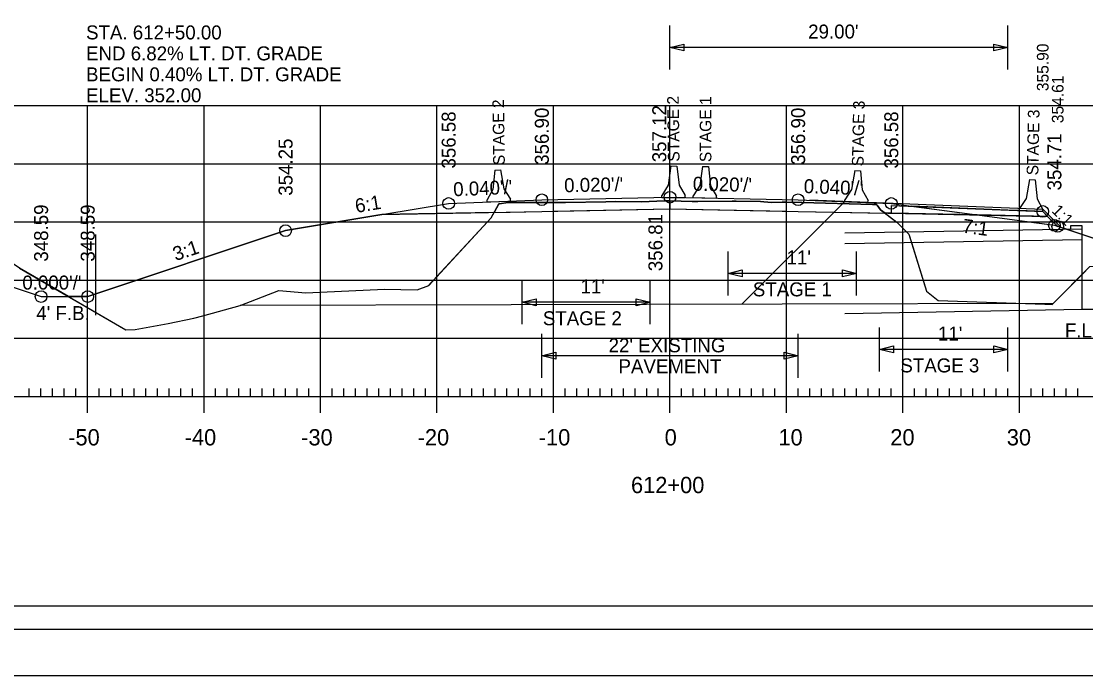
# Model space of a CAD drawing. Extents: x 1368910 to 1369601, y 380116 to 380950.
# Drawn here: x 1369381.9 to 1369473.3, y 380523.8 to 380580 of the extents above; entities that cross this region are included whole.
import ezdxf

# ---------------------------------------------------------------- set-up
doc = ezdxf.new("R2010")
doc.units = 0
for name, color, linetype in [('_STAGE 1 CUT', 7, 'Continuous'), ('_STAGE 1 FILL', 7, 'Continuous'), ('_STAGE 2 CUT', 7, 'Continuous'), ('_STAGE 2 FILL', 7, 'Continuous'), ('_STAGE 3 CUT', 7, 'Continuous'), ('_STAGE 3 FILL', 7, 'Continuous'), ('_STAGE 4 CUT', 7, 'Continuous'), ('Notes', 7, 'Continuous'), ('R_Alt Surface', 7, 'Continuous'), ('R_Axis', 7, 'Continuous'), ('R_Axis Annot', 7, 'Continuous'), ('R_Border', 7, 'Continuous'), ('R_CONC BARRIER', 7, 'Continuous'), ('R_Detour', 7, 'Continuous'), ('R_Detour Surface', 7, 'Continuous'), ('R_Exist Surface', 7, 'Continuous'), ('R_Fin Surface', 7, 'Continuous'), ('R_Grid', 7, 'Continuous'), ('R_No Plot', 7, 'Continuous'), ('R_ROW Annot', 7, 'Continuous'), ('R_Water', 7, 'Continuous'), ('R_Xsect Elev', 7, 'Continuous'), ('R_Xsect Elev Detour', 7, 'Continuous'), ('R_Xsect Slope', 7, 'Continuous')]:
    doc.layers.add(name, color=color, linetype=linetype)

msp = doc.modelspace()

# ---------------------------------------------------------------- linework, layer by layer
at = {"layer": '_STAGE 1 CUT'}
for p, q in [((1369437.59, 380563.882), (1369437.59, 380564.569)), ((1369383.605, 380556.347), (1369385.955, 380556.347))]:
    msp.add_line(p, q, dxfattribs=at)
for points in [[(1369437.59, 380564.569), (1369437.492, 380564.567), (1369437.319, 380564.562), (1369437.081, 380564.558), (1369435.172, 380564.496), (1369432.919, 380564.5), (1369432.093, 380564.495), (1369428.627, 380564.424), (1369428.439, 380564.418), (1369427.59, 380564.423), (1369426.908, 380564.427), (1369426.774, 380564.429), (1369426.749, 380564.429), (1369426.202, 380564.433), (1369423.661, 380564.418), (1369422.964, 380564.304), (1369422.899, 380564.322), (1369422.495, 380563.58)], [(1369422.495, 380563.58), (1369426.59, 380563.662), (1369427.59, 380563.682), (1369437.59, 380563.882)], [(1369385.955, 380556.347), (1369383.513, 380557.759), (1369381.75, 380558.778), (1369379.363, 380560.35), (1369377.59, 380560.372), (1369371.297, 380560.45)], [(1369371.297, 380560.45), (1369377.59, 380558.352), (1369379.37, 380557.759), (1369383.605, 380556.347)]]:
    msp.add_lwpolyline(points, dxfattribs=at)
at = {"layer": '_STAGE 1 FILL'}
for p, q in [((1369417.59, 380563.482), (1369412.863, 380563.388)), ((1369422.495, 380563.58), (1369417.59, 380563.482))]:
    msp.add_line(p, q, dxfattribs=at)
for points in [[(1369385.955, 380556.347), (1369390.879, 380553.501), (1369391.669, 380553.528), (1369394.515, 380554.027), (1369396.729, 380554.484), (1369397.501, 380554.702), (1369400.702, 380555.59), (1369404, 380556.859), (1369406.338, 380556.674), (1369413.073, 380556.969), (1369415.896, 380556.934), (1369416.88, 380557.303), (1369417.3, 380557.759), (1369417.59, 380558.073), (1369421.913, 380562.759), (1369422.243, 380563.116), (1369422.495, 380563.58)], [(1369412.863, 380563.388), (1369409.09, 380562.759), (1369404.59, 380562.009), (1369391.84, 380557.759), (1369387.605, 380556.347), (1369385.955, 380556.347)]]:
    msp.add_lwpolyline(points, dxfattribs=at)
at = {"layer": '_STAGE 2 CUT'}
msp.add_line((1369437.59, 380564.569), (1369437.59, 380563.882), dxfattribs=at)
for points in [[(1369447.53, 380564.453), (1369447.214, 380564.45), (1369446.346, 380564.419), (1369445.651, 380564.495), (1369445.362, 380564.504), (1369443.277, 380564.539), (1369443.146, 380564.539), (1369443.067, 380564.534), (1369442.935, 380564.541), (1369439.984, 380564.51), (1369439.666, 380564.51), (1369439.508, 380564.515), (1369437.598, 380564.569), (1369437.59, 380564.569)], [(1369437.59, 380563.882), (1369447.59, 380563.682), (1369448.59, 380563.662), (1369456.056, 380563.513)], [(1369456.056, 380563.513), (1369455.672, 380563.805), (1369455.386, 380564.2), (1369455.307, 380564.249), (1369454.967, 380564.256), (1369448.941, 380564.413), (1369447.59, 380564.451), (1369447.53, 380564.453)]]:
    msp.add_lwpolyline(points, dxfattribs=at)
at = {"layer": '_STAGE 2 FILL'}
for p, q in [((1369470.012, 380563.234), (1369463.958, 380563.355)), ((1369470.874, 380562.371), (1369470.012, 380563.234)), ((1369471.537, 380562.15), (1369470.874, 380562.371))]:
    msp.add_line(p, q, dxfattribs=at)
for points in [[(1369463.958, 380563.355), (1369456.59, 380563.502), (1369456.056, 380563.513)], [(1369456.056, 380563.513), (1369457.057, 380562.748), (1369457.897, 380561.909), (1369458.106, 380561.7), (1369458.321, 380561), (1369459.613, 380556.8), (1369460.62, 380555.998), (1369469.774, 380555.696), (1369470.411, 380555.657), (1369470.476, 380555.744), (1369472.967, 380558.244), (1369473.638, 380558.918), (1369479.503, 380559.495)], [(1369479.503, 380559.495), (1369472.967, 380561.674), (1369471.537, 380562.15)]]:
    msp.add_lwpolyline(points, dxfattribs=at)
at = {"layer": '_STAGE 3 CUT'}
for p, q in [((1369437.59, 380563.882), (1369437.59, 380564.569)), ((1369385.955, 380556.347), (1369381.75, 380558.778))]:
    msp.add_line(p, q, dxfattribs=at)
for points in [[(1369437.59, 380564.569), (1369437.492, 380564.567), (1369437.319, 380564.562), (1369437.081, 380564.558), (1369435.172, 380564.496), (1369432.919, 380564.5), (1369432.093, 380564.495), (1369428.627, 380564.424), (1369428.439, 380564.418), (1369426.908, 380564.427), (1369426.774, 380564.429), (1369426.749, 380564.429), (1369426.202, 380564.433), (1369423.661, 380564.418), (1369422.964, 380564.304), (1369422.899, 380564.322), (1369422.495, 380563.58)], [(1369422.495, 380563.58), (1369426.59, 380563.662), (1369437.59, 380563.882)], [(1369371.297, 380560.45), (1369383.605, 380556.347), (1369385.955, 380556.347)]]:
    msp.add_lwpolyline(points, dxfattribs=at)
at = {"layer": '_STAGE 3 FILL'}
msp.add_line((1369422.495, 380563.58), (1369412.863, 380563.388), dxfattribs=at)
for points in [[(1369385.955, 380556.347), (1369390.879, 380553.501), (1369391.669, 380553.528), (1369394.515, 380554.027), (1369396.729, 380554.484), (1369397.501, 380554.702), (1369400.702, 380555.59), (1369404, 380556.859), (1369406.338, 380556.674), (1369413.073, 380556.969), (1369415.896, 380556.934), (1369416.88, 380557.303), (1369422.243, 380563.116), (1369422.495, 380563.58)], [(1369412.863, 380563.388), (1369404.59, 380562.009), (1369387.605, 380556.347), (1369385.955, 380556.347)]]:
    msp.add_lwpolyline(points, dxfattribs=at)
at = {"layer": '_STAGE 4 CUT'}
for p, q in [((1369467.59, 380563.735), (1369467.59, 380563.735)), ((1369470.59, 380562.466), (1369470.874, 380562.371))]:
    msp.add_line(p, q, dxfattribs=at)
for points in [[(1369467.59, 380563.735), (1369466.59, 380563.775), (1369458.363, 380564.104)], [(1369458.363, 380564.104), (1369463.958, 380563.355), (1369467.59, 380562.868), (1369468.405, 380562.759), (1369470.59, 380562.466)], [(1369467.592, 380563.735), (1369467.59, 380563.735)], [(1369470.874, 380562.371), (1369470.487, 380562.759), (1369470.182, 380563.064), (1369469.59, 380563.655), (1369467.592, 380563.735)]]:
    msp.add_lwpolyline(points, dxfattribs=at)
at = {"layer": 'R_Alt Surface'}
for points in [[(1369412.863, 380563.388), (1369426.59, 380563.662), (1369437.59, 380563.882), (1369448.59, 380563.662), (1369463.958, 380563.355)], [(1369456.59, 380564.175), (1369456.59, 380563.502), (1369470.012, 380563.234)]]:
    msp.add_lwpolyline(points, dxfattribs=at)
at = {"layer": 'R_Axis'}
for p, q in [((1369387.59, 380546.359), (1369387.59, 380549.159)), ((1369397.59, 380546.359), (1369397.59, 380549.159)), ((1369407.59, 380546.359), (1369407.59, 380549.159)), ((1369417.59, 380546.359), (1369417.59, 380549.159)), ((1369427.59, 380546.359), (1369427.59, 380549.159)), ((1369437.59, 380546.359), (1369437.59, 380549.159)), ((1369447.59, 380546.359), (1369447.59, 380549.159)), ((1369457.59, 380546.359), (1369457.59, 380549.159)), ((1369467.59, 380546.359), (1369467.59, 380549.159)), ((1369382.59, 380547.759), (1369382.59, 380548.459)), ((1369383.59, 380547.759), (1369383.59, 380548.459)), ((1369384.59, 380547.759), (1369384.59, 380548.459)), ((1369385.59, 380547.759), (1369385.59, 380548.459)), ((1369386.59, 380547.759), (1369386.59, 380548.459)), ((1369388.59, 380547.759), (1369388.59, 380548.459)), ((1369389.59, 380547.759), (1369389.59, 380548.459)), ((1369390.59, 380547.759), (1369390.59, 380548.459)), ((1369391.59, 380547.759), (1369391.59, 380548.459)), ((1369392.59, 380547.759), (1369392.59, 380548.459)), ((1369393.59, 380547.759), (1369393.59, 380548.459)), ((1369394.59, 380547.759), (1369394.59, 380548.459)), ((1369395.59, 380547.759), (1369395.59, 380548.459)), ((1369396.59, 380547.759), (1369396.59, 380548.459)), ((1369398.59, 380547.759), (1369398.59, 380548.459)), ((1369399.59, 380547.759), (1369399.59, 380548.459)), ((1369400.59, 380547.759), (1369400.59, 380548.459)), ((1369401.59, 380547.759), (1369401.59, 380548.459)), ((1369402.59, 380547.759), (1369402.59, 380548.459)), ((1369403.59, 380547.759), (1369403.59, 380548.459)), ((1369404.59, 380547.759), (1369404.59, 380548.459)), ((1369405.59, 380547.759), (1369405.59, 380548.459)), ((1369406.59, 380547.759), (1369406.59, 380548.459)), ((1369408.59, 380547.759), (1369408.59, 380548.459)), ((1369409.59, 380547.759), (1369409.59, 380548.459)), ((1369410.59, 380547.759), (1369410.59, 380548.459)), ((1369411.59, 380547.759), (1369411.59, 380548.459)), ((1369412.59, 380547.759), (1369412.59, 380548.459)), ((1369413.59, 380547.759), (1369413.59, 380548.459)), ((1369414.59, 380547.759), (1369414.59, 380548.459)), ((1369415.59, 380547.759), (1369415.59, 380548.459)), ((1369416.59, 380547.759), (1369416.59, 380548.459)), ((1369418.59, 380547.759), (1369418.59, 380548.459)), ((1369419.59, 380547.759), (1369419.59, 380548.459)), ((1369420.59, 380547.759), (1369420.59, 380548.459)), ((1369421.59, 380547.759), (1369421.59, 380548.459)), ((1369422.59, 380547.759), (1369422.59, 380548.459)), ((1369423.59, 380547.759), (1369423.59, 380548.459)), ((1369424.59, 380547.759), (1369424.59, 380548.459)), ((1369425.59, 380547.759), (1369425.59, 380548.459)), ((1369426.59, 380547.759), (1369426.59, 380548.459)), ((1369428.59, 380547.759), (1369428.59, 380548.459)), ((1369429.59, 380547.759), (1369429.59, 380548.459)), ((1369430.59, 380547.759), (1369430.59, 380548.459)), ((1369431.59, 380547.759), (1369431.59, 380548.459)), ((1369432.59, 380547.759), (1369432.59, 380548.459)), ((1369433.59, 380547.759), (1369433.59, 380548.459)), ((1369434.59, 380547.759), (1369434.59, 380548.459)), ((1369435.59, 380547.759), (1369435.59, 380548.459)), ((1369436.59, 380547.759), (1369436.59, 380548.459)), ((1369438.59, 380547.759), (1369438.59, 380548.459)), ((1369439.59, 380547.759), (1369439.59, 380548.459)), ((1369440.59, 380547.759), (1369440.59, 380548.459)), ((1369441.59, 380547.759), (1369441.59, 380548.459)), ((1369442.59, 380547.759), (1369442.59, 380548.459)), ((1369443.59, 380547.759), (1369443.59, 380548.459)), ((1369444.59, 380547.759), (1369444.59, 380548.459)), ((1369445.59, 380547.759), (1369445.59, 380548.459)), ((1369446.59, 380547.759), (1369446.59, 380548.459)), ((1369448.59, 380547.759), (1369448.59, 380548.459)), ((1369449.59, 380547.759), (1369449.59, 380548.459)), ((1369450.59, 380547.759), (1369450.59, 380548.459)), ((1369451.59, 380547.759), (1369451.59, 380548.459)), ((1369452.59, 380547.759), (1369452.59, 380548.459)), ((1369453.59, 380547.759), (1369453.59, 380548.459)), ((1369454.59, 380547.759), (1369454.59, 380548.459)), ((1369455.59, 380547.759), (1369455.59, 380548.459)), ((1369456.59, 380547.759), (1369456.59, 380548.459)), ((1369458.59, 380547.759), (1369458.59, 380548.459)), ((1369459.59, 380547.759), (1369459.59, 380548.459)), ((1369460.59, 380547.759), (1369460.59, 380548.459)), ((1369461.59, 380547.759), (1369461.59, 380548.459)), ((1369462.59, 380547.759), (1369462.59, 380548.459)), ((1369463.59, 380547.759), (1369463.59, 380548.459)), ((1369464.59, 380547.759), (1369464.59, 380548.459)), ((1369465.59, 380547.759), (1369465.59, 380548.459)), ((1369466.59, 380547.759), (1369466.59, 380548.459)), ((1369468.59, 380547.759), (1369468.59, 380548.459)), ((1369469.59, 380547.759), (1369469.59, 380548.459)), ((1369470.59, 380547.759), (1369470.59, 380548.459)), ((1369471.59, 380547.759), (1369471.59, 380548.459)), ((1369472.59, 380547.759), (1369472.59, 380548.459)), ((1369297.59, 380547.759), (1369577.59, 380547.759))]:
    msp.add_line(p, q, dxfattribs=at)
at = {"layer": 'R_Border'}
msp.add_line((1369595.77, 380527.759), (1369279.59, 380527.759), dxfattribs=at)
at = {"layer": 'R_CONC BARRIER'}
for p, q in [((1369437.669, 380567.563), (1369438.169, 380567.559)), ((1369440.394, 380567.527), (1369440.894, 380567.517)), ((1369422.542, 380567.202), (1369423.042, 380567.222)), ((1369453.447, 380567.17), (1369453.947, 380567.15)), ((1369468.449, 380566.403), (1369468.948, 380566.383)), ((1369421.901, 380564.474), (1369421.894, 380564.641)), ((1369423.899, 380564.554), (1369423.893, 380564.721)), ((1369436.9, 380564.868), (1369436.901, 380565.035)), ((1369436.9, 380564.868), (1369438.9, 380564.854)), ((1369438.9, 380564.854), (1369438.901, 380565.021)), ((1369439.59, 380564.842), (1369439.593, 380565.009)), ((1369439.59, 380564.842), (1369441.59, 380564.802)), ((1369441.59, 380564.802), (1369441.593, 380564.969)), ((1369452.59, 380564.502), (1369452.597, 380564.669)), ((1369454.588, 380564.422), (1369454.595, 380564.589)), ((1369421.901, 380564.474), (1369423.899, 380564.554)), ((1369452.59, 380564.502), (1369454.588, 380564.422)), ((1369467.592, 380563.735), (1369467.598, 380563.902)), ((1369467.592, 380563.735), (1369469.59, 380563.655)), ((1369469.59, 380563.655), (1369469.597, 380563.822))]:
    msp.add_line(p, q, dxfattribs=at)
for points in [[(1369437.669, 380567.563), (1369437.439, 380565.922), (1369436.901, 380565.035)], [(1369438.169, 380567.559), (1369438.376, 380565.915), (1369438.901, 380565.021)], [(1369440.394, 380567.527), (1369440.142, 380565.889), (1369439.593, 380565.009)], [(1369440.894, 380567.517), (1369441.079, 380565.87), (1369441.593, 380564.969)], [(1369422.542, 380567.202), (1369422.39, 380565.552), (1369421.894, 380564.641)], [(1369423.042, 380567.222), (1369423.326, 380565.59), (1369423.893, 380564.721)], [(1369453.447, 380567.17), (1369453.163, 380565.537), (1369452.597, 380564.669)], [(1369453.947, 380567.15), (1369454.1, 380565.5), (1369454.595, 380564.589)], [(1369468.449, 380566.403), (1369468.165, 380564.771), (1369467.598, 380563.902)], [(1369468.948, 380566.383), (1369469.101, 380564.733), (1369469.597, 380563.822)]]:
    msp.add_lwpolyline(points, dxfattribs=at)
at = {"layer": 'R_Detour'}
for p, q in [((1369449.59, 380564.642), (1369469.59, 380563.842)), ((1369452.59, 380564.522), (1369443.753, 380555.685)), ((1369469.59, 380563.842), (1369471.11, 380562.322)), ((1369388.286, 380561.678), (1369388.286, 380554.762)), ((1369470.476, 380555.744), (1369400.702, 380555.59))]:
    msp.add_line(p, q, dxfattribs=at)
at = {"layer": 'R_Detour Surface'}
msp.add_lwpolyline([(1369456.59, 380564.175), (1369469.59, 380563.655), (1369470.012, 380563.234), (1369470.874, 380562.371)], dxfattribs=at)
at = {"layer": 'R_Exist Surface'}
msp.add_lwpolyline([(1369381.75, 380558.778), (1369390.879, 380553.501), (1369391.669, 380553.528), (1369394.515, 380554.027), (1369396.729, 380554.484), (1369397.501, 380554.702), (1369400.702, 380555.59), (1369404, 380556.859), (1369406.338, 380556.674), (1369413.073, 380556.969), (1369415.896, 380556.934), (1369416.88, 380557.303), (1369422.243, 380563.116), (1369422.899, 380564.322), (1369422.964, 380564.304), (1369423.661, 380564.418), (1369426.202, 380564.433), (1369426.749, 380564.429), (1369426.774, 380564.429), (1369426.908, 380564.427), (1369428.439, 380564.418), (1369428.627, 380564.424), (1369432.093, 380564.495), (1369432.919, 380564.5), (1369435.172, 380564.496), (1369437.081, 380564.558), (1369437.319, 380564.562), (1369437.492, 380564.567), (1369437.598, 380564.569), (1369439.508, 380564.515), (1369439.666, 380564.51), (1369439.984, 380564.51), (1369442.935, 380564.541), (1369443.067, 380564.534), (1369443.146, 380564.539), (1369443.277, 380564.539), (1369445.362, 380564.504), (1369445.651, 380564.495), (1369446.346, 380564.419), (1369447.214, 380564.45), (1369447.53, 380564.453), (1369448.941, 380564.413), (1369454.967, 380564.256), (1369455.307, 380564.249), (1369455.386, 380564.2), (1369455.672, 380563.805), (1369457.057, 380562.748), (1369458.106, 380561.7), (1369459.613, 380556.8), (1369460.62, 380555.998), (1369469.774, 380555.696), (1369470.411, 380555.657), (1369470.476, 380555.744), (1369473.638, 380558.918)], dxfattribs=at)
at = {"layer": 'R_Fin Surface'}
msp.add_lwpolyline([(1369371.297, 380560.45), (1369383.605, 380556.347), (1369387.605, 380556.347), (1369404.59, 380562.009), (1369412.863, 380563.388), (1369418.59, 380564.342), (1369426.59, 380564.662), (1369437.59, 380564.882), (1369448.59, 380564.662), (1369456.59, 380564.342), (1369463.958, 380563.355), (1369470.59, 380562.466), (1369492.212, 380555.259), (1369500.212, 380555.259), (1369512.393, 380559.319)], dxfattribs=at)
at = {"layer": 'R_Grid'}
for p, q in [((1369297.59, 380572.759), (1369577.59, 380572.759)), ((1369387.59, 380547.759), (1369387.59, 380572.759)), ((1369397.59, 380547.759), (1369397.59, 380572.759)), ((1369407.59, 380547.759), (1369407.59, 380572.759)), ((1369417.59, 380547.759), (1369417.59, 380572.759)), ((1369427.59, 380547.759), (1369427.59, 380572.759)), ((1369437.59, 380547.759), (1369437.59, 380572.759)), ((1369447.59, 380547.759), (1369447.59, 380572.759)), ((1369457.59, 380547.759), (1369457.59, 380572.759)), ((1369467.59, 380547.759), (1369467.59, 380572.759)), ((1369297.59, 380567.759), (1369577.59, 380567.759)), ((1369297.59, 380562.759), (1369577.59, 380562.759)), ((1369297.59, 380557.759), (1369577.59, 380557.759)), ((1369297.59, 380552.759), (1369577.59, 380552.759)), ((1369297.59, 380547.759), (1369577.59, 380547.759))]:
    msp.add_line(p, q, dxfattribs=at)
at = {"layer": 'R_No Plot'}
for points in [[(1369267.182, 380737.113), (1369600.522, 380737.113), (1369600.522, 380523.776), (1369267.182, 380523.776)], [(1369281.59, 380731.219), (1369531.13, 380731.219), (1369531.13, 380721.339), (1369548.67, 380721.339), (1369572.77, 380721.339), (1369572.77, 380699.006), (1369593.77, 380699.006), (1369593.77, 380529.759), (1369281.59, 380529.759)], [(1369281.59, 380628.489), (1369593.77, 380628.489), (1369593.77, 380529.759), (1369281.59, 380529.759)]]:
    msp.add_lwpolyline(points, close=True, dxfattribs=at)
for centre in [(1369418.59, 380564.342), (1369426.59, 380564.662), (1369437.59, 380564.882), (1369448.59, 380564.662), (1369456.59, 380564.342), (1369469.59, 380563.655), (1369470.59, 380562.466), (1369470.874, 380562.371), (1369404.59, 380562.009), (1369383.605, 380556.347), (1369387.605, 380556.347)]:
    msp.add_circle(centre, 0.5, dxfattribs=at)
at = {"layer": 'R_ROW Annot'}
for p, q in [((1369437.59, 380575.857), (1369437.59, 380579.625)), ((1369466.59, 380575.857), (1369466.59, 380579.625)), ((1369466.59, 380577.741), (1369437.59, 380577.741)), ((1369442.59, 380556.451), (1369442.59, 380560.219)), ((1369453.59, 380556.451), (1369453.59, 380560.219)), ((1369453.59, 380558.335), (1369442.59, 380558.335)), ((1369424.899, 380553.968), (1369424.899, 380557.736)), ((1369435.899, 380553.968), (1369435.899, 380557.736)), ((1369435.899, 380555.852), (1369424.899, 380555.852)), ((1369455.59, 380549.916), (1369455.59, 380553.684)), ((1369466.59, 380549.916), (1369466.59, 380553.684)), ((1369426.59, 380549.372), (1369426.59, 380553.141)), ((1369448.59, 380549.372), (1369448.59, 380553.141)), ((1369466.59, 380551.8), (1369455.59, 380551.8)), ((1369448.59, 380551.257), (1369426.59, 380551.257))]:
    msp.add_line(p, q, dxfattribs=at)
for points in [[(1369438.79, 380577.441), (1369437.59, 380577.741), (1369438.79, 380578.041)], [(1369465.39, 380578.041), (1369466.59, 380577.741), (1369465.39, 380577.441)], [(1369443.79, 380558.035), (1369442.59, 380558.335), (1369443.79, 380558.635)], [(1369452.39, 380558.635), (1369453.59, 380558.335), (1369452.39, 380558.035)], [(1369426.099, 380555.552), (1369424.899, 380555.852), (1369426.099, 380556.152)], [(1369434.699, 380556.152), (1369435.899, 380555.852), (1369434.699, 380555.552)], [(1369456.79, 380551.5), (1369455.59, 380551.8), (1369456.79, 380552.1)], [(1369465.39, 380552.1), (1369466.59, 380551.8), (1369465.39, 380551.5)], [(1369427.79, 380550.957), (1369426.59, 380551.257), (1369427.79, 380551.557)], [(1369447.39, 380551.557), (1369448.59, 380551.257), (1369447.39, 380550.957)]]:
    msp.add_lwpolyline(points, close=True, dxfattribs=at)
at = {"layer": 'R_Water'}
for p, q in [((1369452.59, 380561.816), (1369472.967, 380562.175)), ((1369452.59, 380560.899), (1369472.967, 380561.259)), ((1369452.59, 380554.899), (1369472.967, 380555.259))]:
    msp.add_line(p, q, dxfattribs=at)
for points in [[(1369472.967, 380555.259), (1369472.967, 380561.259), (1369472.967, 380562.175), (1369472.967, 380562.425), (1369471.967, 380562.425), (1369471.967, 380562.175)], [(1369472.967, 380555.259), (1369487.467, 380555.259), (1369487.467, 380556.84)]]:
    msp.add_lwpolyline(points, dxfattribs=at)

# ---------------------------------------------------------------- texts
at = {"layer": 'Notes'}
for s, p in [('STA. 612+50.00', (1369387.463, 380578.435)), ('END 6.82% LT. DT. GRADE', (1369387.463, 380576.635)), ('BEGIN 0.40% LT. DT. GRADE', (1369387.463, 380574.835)), ('ELEV. 352.00', (1369387.463, 380573.035))]:
    msp.add_text(s, height=1.2, dxfattribs=at).set_placement(p)
at = {"layer": 'R_Axis Annot'}
for s, p in [('-50', (1369385.931, 380543.559)), ('-40', (1369395.931, 380543.559)), ('-30', (1369405.931, 380543.559)), ('-20', (1369415.931, 380543.559)), ('-10', (1369426.328, 380543.559)), ('0', (1369437.132, 380543.559)), ('10', (1369446.901, 380543.559)), ('20', (1369456.504, 380543.559)), ('30', (1369466.504, 380543.559)), ('612+00', (1369434.244, 380539.459))]:
    msp.add_text(s, height=1.4, dxfattribs=at).set_placement(p)
at = {"layer": 'R_CONC BARRIER'}
for s, rotation, p in [(' STAGE 2', 90.73399, (1369423.419, 380567.268)), (' STAGE 2', 90.73399, (1369438.419, 380567.567)), (' STAGE 1', 90, (1369441.144, 380567.522)), (' STAGE 3', 88.85515, (1369454.197, 380567.15)), (' STAGE 3', 88.85515, (1369469.199, 380566.383))]:
    msp.add_text(s, height=1, rotation=rotation, dxfattribs=at).set_placement(p)
at = {"layer": 'R_ROW Annot'}
for s, p in [("29.00'", (1369449.454, 380578.511)), ("11'", (1369447.599, 380559.104)), ("11'", (1369429.908, 380556.622)), ('STAGE 1', (1369444.707, 380556.365)), ('STAGE 2', (1369426.676, 380553.882)), ("11'", (1369460.599, 380552.57)), ("22' EXISTING", (1369432.322, 380551.557)), ('PAVEMENT', (1369433.173, 380549.757)), ('STAGE 3', (1369457.367, 380549.83))]:
    msp.add_text(s, height=1.2, dxfattribs=at).set_placement(p)
at = {"layer": 'R_Xsect Elev'}
for s, p in [('356.58', (1369419.19, 380567.342)), ('356.90', (1369427.19, 380567.662)), ('357.12', (1369437.272, 380567.882)), ('356.90', (1369449.19, 380567.662)), ('356.58', (1369457.19, 380567.342)), ('354.71', (1369471.19, 380565.466)), ('354.25', (1369405.19, 380565.009)), ('348.59', (1369384.205, 380559.347)), ('348.59', (1369388.205, 380559.347)), ('356.81', (1369436.94, 380558.527))]:
    msp.add_text(s, height=1.2, rotation=90, dxfattribs=at).set_placement(p)
at = {"layer": 'R_Xsect Elev Detour'}
for s, p in [('355.90', (1369470.09, 380573.99)), ('354.61', (1369471.374, 380571.239))]:
    msp.add_text(s, height=1, rotation=90, dxfattribs=at).set_placement(p)
at = {"layer": 'R_Xsect Slope'}
for s, height, rotation, p in [("0.040'/'", 1.2, 2.29061, (1369419.007, 380564.959)), ("0.020'/'", 1.2, 1.14576, (1369428.516, 380565.301)), ("0.020'/'", 1.2, 358.85424, (1369439.54, 380565.443)), ("0.040'/'", 1.2, 357.70939, (1369449.055, 380565.244)), ('6:1', 1.2, 9.46234, (1369410.66, 380563.527)), ('1:1', 1, 315, (1369470.296, 380563.656)), ('7:1', 1.2, 352.36745, (1369462.64, 380561.845)), ('3:1', 1.2, 18.43493, (1369395.15, 380559.389)), ("0.000'/'", 1.2, 360, (1369381.995, 380556.947)), ("4' F.B.", 1.2, 360, (1369383.194, 380554.327)), ("4' F.B.", 1.2, 360, (1369383.194, 380554.327)), ('F.L. INLET = 347.50', 1.2, 360, (1369471.492, 380552.839))]:
    msp.add_text(s, height=height, rotation=rotation, dxfattribs=at).set_placement(p)

doc.saveas('drawing.dxf')
